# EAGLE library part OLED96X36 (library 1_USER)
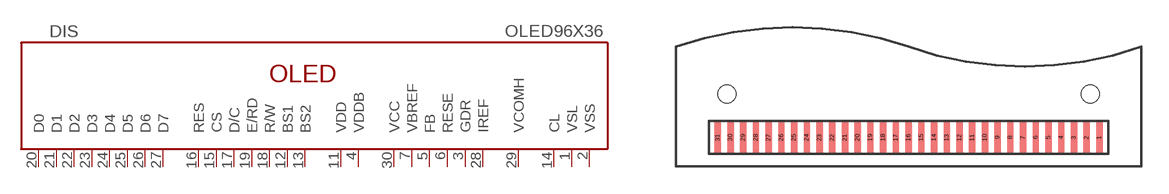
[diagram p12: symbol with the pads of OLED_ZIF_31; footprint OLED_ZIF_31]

Designator prefix DIS

## OLED96X36  [OLED_ZIF_31]
1  VSL
2  VSS
3  GDR
4  VDDB
5  FB
6  RESE  pwr
7  VBREF  pwr
11  VDD
12  BS1  in
13  BS2  in
14  CL
15  CS  in
16  RES  in
17  D/C  in
18  R/W  in
19  E/RD  in
20  D0
21  D1
22  D2
23  D3
24  D4
25  D5
26  D6
27  D7
28  IREF
29  VCOMH
30  VCC

## Footprint OLED_ZIF_31 (pad centres in mm)
smd 0.35 x 1.8: 1 10.5,0; 2 9.8,0; 3 9.1,0; 4 8.4,0; 5 7.7,0; 6 7,0; 7 6.3,0; 8 5.6,0; 9 4.9,0; 10 4.2,0; 11 3.5,0; 12 2.8,0; 13 2.1,0; 14 1.4,0; 15 0.7,0; 16 0,0; 17 -0.7,0; 18 -1.4,0; 19 -2.1,0; 20 -2.8,0; 21 -3.5,0; 22 -4.2,0; 23 -4.9,0; 24 -5.6,0; 25 -6.3,0; 26 -7,0; 27 -7.7,0; 28 -8.4,0; 29 -9.1,0; 30 -9.8,0; 31 -10.5,0
hole 1 at -10,2.4
hole 1 at 10,2.4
